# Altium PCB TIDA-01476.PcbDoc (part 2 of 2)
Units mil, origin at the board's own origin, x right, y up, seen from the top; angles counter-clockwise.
Board outline 2952.76 x 1377.95 mil, 4 copper layers (Layer 1 - Top Layer, Layer 2 - GND, Layer 3 - PWR, Layer 4 - Bottom Layer), stack 32.668 mil thick; 140 components, 50 nets, 358 pads, 357 vias.
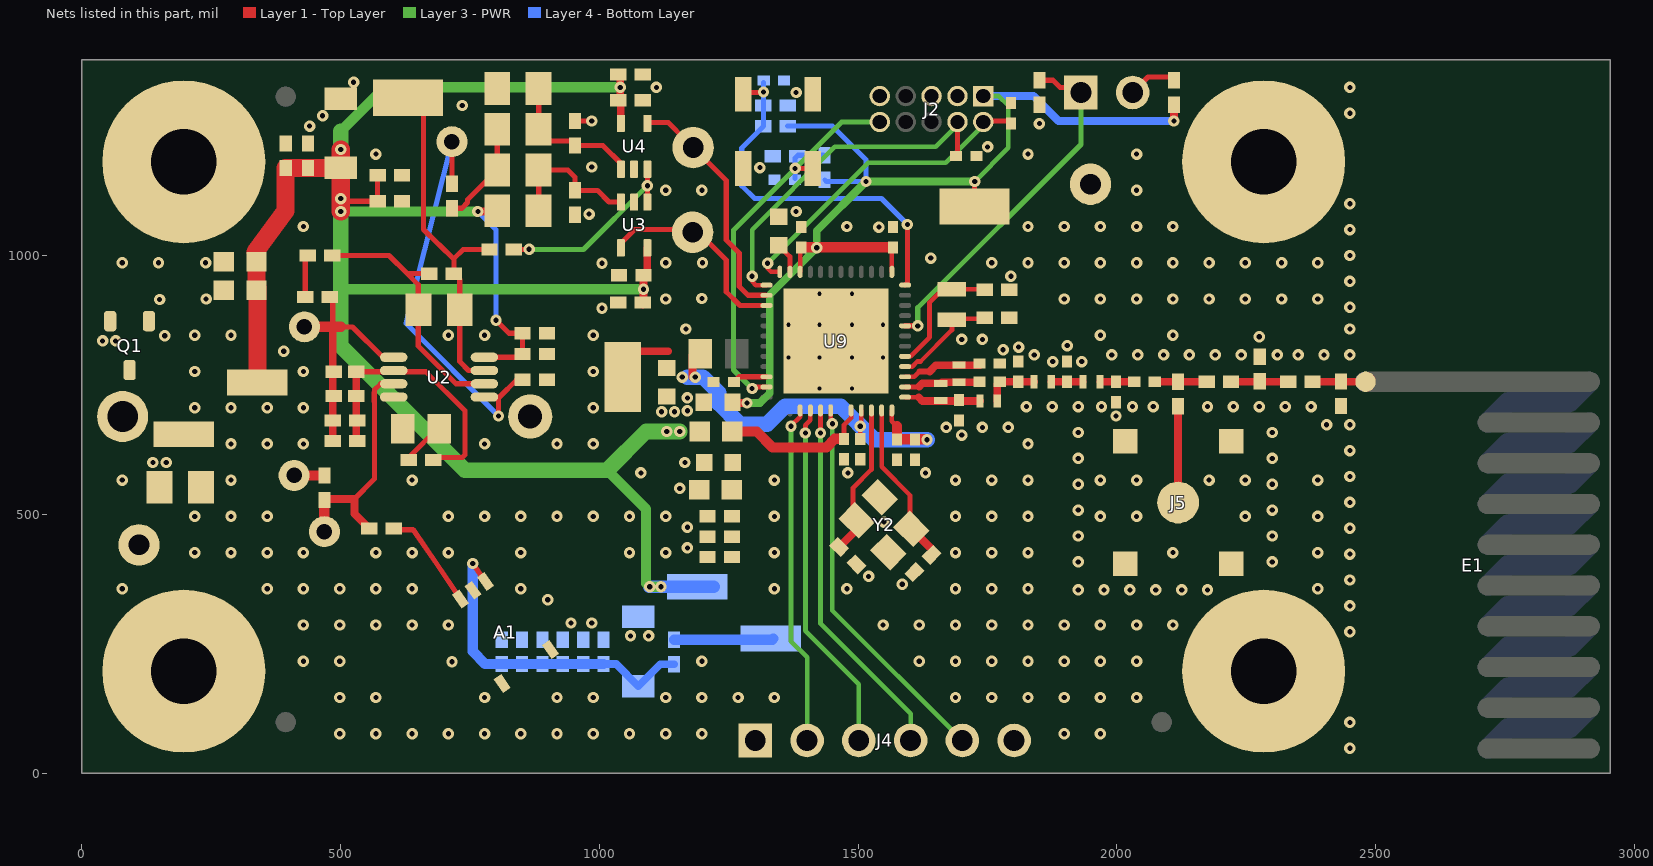
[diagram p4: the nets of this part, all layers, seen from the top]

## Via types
v1: diameter 22, hole 10, Layer 1 - Top Layer to Layer 4 - Bottom Layer, tented both sides, 323 vias
v2: diameter 39.37, hole 14.96, Layer 1 - Top Layer to Layer 4 - Bottom Layer, 19 vias
v3: diameter 19.68, hole 7.87, Layer 1 - Top Layer to Layer 4 - Bottom Layer, 12 vias
v4: diameter 22, hole 10, Layer 1 - Top Layer to Layer 4 - Bottom Layer, 3 vias

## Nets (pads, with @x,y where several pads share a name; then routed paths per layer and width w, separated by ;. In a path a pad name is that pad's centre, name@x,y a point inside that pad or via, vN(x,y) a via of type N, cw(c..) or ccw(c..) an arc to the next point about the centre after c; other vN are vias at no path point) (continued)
GND: A1.2 A1.4 A1.5 BT1.2 C1.2 C2.2 C3.2 C4.2 C5.2 C6.2 C7.2 C8.2 C9.2 C10.2 C11.2 C12.2 C13.2 C14.1 C16.1 C18.1 C19.2 C20.1 C22.2 C23.2 C24.1 C25.2 C26.2 C27.2 C28.2 C29.2 C30.1 C31.2 C32.2 C33.2 C34.2 C35.2 C36.2 C37.2 C38.2 C39.2 C40.1 C41.1 C42.1 C43.1 C44.2 C45.2 C46.2 C48.2 C49.2 C50.2 C53.2 C54.2 C55.2 C56.2 C57.2 H1.1 H4.1 H6.1 H8.1 J2.3 J2.5 J2.9 J4.1 J4.6 J5.2 J5.3 J5.4 J5.5 L8.2 pad.0@410,575 Q1.1 R4.1 R11.1 R15.1 S1.1 S2.1 TP1.1 TP2.1 U2.4 U3.2 U4.2 U5.2 U6.2 U7.2 U8.2 U9.49 Y2.2 Y2.4 | length 90.6
  Layer 1 - Top Layer w10: C23.2@952.76,1259.84 v1@984.84,1259.84
  Layer 1 - Top Layer w20: pad.0@410,575 R4.1@468.5,574.8
  other v1: 2450,48 498,76 568,76 638,76 708,76 778,76 848,76 918,76 988,76 1058,76 1128,76 1198,76 1898,76 1968,76 2450,98 498,146 568,146 778,146 918,146 988,146 1128,146 1198,146 1268,146 1338,146 1688,146 1758,146 1828,146 1898,146 1968,146 2038,146 715,215 428,216 498,216 1198,216 1618,216 1688,216 1758,216 1828,216 1898,216 1968,216 2038,216 1060,265 1095,265 2450,273 428,286 498,286 568,286 638,286 708,286 1548,286 1618,286 1688,286 1758,286 1828,286 1898,286 1968,286 2038,286 2108,286 945,290 985,290 2450,323 900,335 1925,354 1975,354 2025,354 2075,354 2125,354 2175,354 78,356 358,356 428,356 498,356 568,356 638,356 848,356 1338,356 1478,356 1688,356 1758,356 1828,356 2388,356 1585,365 2450,373 1520,380 1925,408 2300,408 2450,423 218,426 288,426 358,426 428,426 568,426 638,426 708,426 848,426 1058,426 1128,426 1338,426 1688,426 1758,426 1828,426 2108,426 2388,426 1170,435 1925,458 2300,458 2450,473 1170,475 1550,485 218,496 288,496 358,496 708,496 778,496 848,496 918,496 988,496 1058,496 1128,496 1338,496 1688,496 1758,496 1828,496 1968,496 2038,496 2248,496 2388,496 1925,508 2300,508 2450,523 1155,550 1925,558 2300,558 78,566 288,566 638,566 1338,566 1688,566 1758,566 1828,566 1968,566 2038,566 2178,566 2248,566 2388,566 2450,573 1080,580 1480,580 1630,580 1165,600 1925,608 2300,608 2450,623 288,636 358,636 428,636 778,636 918,636 988,636 1828,636 1700,653 1925,658 2300,658 1670,668 1740,668 1790,668 2405,673 2450,673 1998,690 1120,698 1145,698 1170,700 218,706 288,706 358,706 428,706 988,706 1825,708 1875,708 1925,708 1970,708 2030,708 2070,708 2175,708 2225,708 2275,708 2325,708 2375,708 1170,725 218,776 428,776 988,776 1876,795 1932,795 1840,808 1990,808 2040,808 2090,808 2140,808 2190,808 2240,808 2310,808 2350,808 2400,808 2450,808 390,815 1780,818 1810,823 1904,826 1700,838 1740,838 2275,843 160,845 218,846 288,846 708,846 778,846 988,846 1968,846 2108,846 1167,858 2450,858 1005,898 2450,900 150,915 240,916 1128,916 1898,916 1968,916 2038,916 2108,916 2178,916 2248,916 2318,916 2388,916 1198,917 2450,950 1795,960 1005,985 78,986 148,986 239,986 1128,986 1199,986 1758,986 1828,986 1898,986 1968,986 2038,986 2108,986 2178,986 2248,986 2318,986 2388,986 2450,1000 2450,1050 1540,1055 428,1056 1478,1056 1828,1056 1898,1056 1968,1056 2038,1056 2108,1056 980,1080 1380,1085 2450,1100 1128,1126 1198,1126 2038,1126 1310,1170 985,1171 568,1196 1828,1196 2038,1196 1750,1210 440,1250 1850,1255 985,1260 465,1270 2450,1275 1380,1315 1110,1325 2450,1325 525,1335
  other v3: 1425.06,743.11 1488.33,743.11 1365.16,803.01 1425.06,803.01 1488.33,803.01 1548.23,803.01 1365.16,866.28 1425.06,866.28 1488.33,866.28 1548.23,866.28 1425.06,926.18 1488.33,926.18
  other v4: 1640,995 735,1290
JTAG_TCK: J2.4 U7.1 U9.25 | length 676.6
  Layer 1 - Top Layer w9: v1(1295,960) 1295,950 1302.09,942.91 U9.25@1322.83,942.91 ; U7.1@1691.73,1192.6 J2.4@1691.73,1258.15
  Layer 3 - PWR w9: v1(1295,960) 1295,1050 1455,1210 1650,1210 J2.4@1691.73,1251.73
JTAG_TMS: J2.2 U6.1 U9.24 | length 611.6
  Layer 1 - Top Layer w9: v1(1325,985) 1325,975 1331.5,968.5 U9.24@1348.43,968.5 ; J2.2@1746.77,1260 U6.1@1795,1260
  Layer 3 - PWR w9: v1(1325,985) 1519,1179 1669,1179 J2.2@1741.73,1251.73
MODE_SELECTION: J3.1 R15.2 U9.8 | length 695.5
  Layer 1 - Top Layer w10: U9.8@1590.55,864.17 v1@1614.83,864.17 ; R15.2@1850.39,1338.58 1876.42,1338.58 1890,1325 1920.28,1325 J3.1@1930.32,1314.96
  Layer 3 - PWR w10: v1(1615,864) 1615,899 1930.32,1214.32 J3.1@1930.32,1314.96
NetA1_1: A1.1 C3.1 C5.1 C7.1 C9.1 C11.1 C12.1 C55.1 R2.1 | length 641.4
  Layer 1 - Top Layer w10: v1(755,405) A1.1@776.51,374.67
  Layer 4 - Bottom Layer w15: C3.1@1007.89,210.63 1032.44,210.63 C55.1@1075,168.07 1117.31,210.38 R2.1@1144,210.38
  Layer 4 - Bottom Layer w20: v1(755,405) 755,235 779.37,210.63 C12.1@811.04,210.63 C11.1@850.41,210.63 C7.1@929.15,210.63 C3.1@1007.89,210.63
NetA1_3: A1.3 R18.1 | length 195.1
  Layer 1 - Top Layer w10: R18.1@602.36,472.44 604.8,470 640,470 685,405 A1.3@728.14,340.8
NetBT1_1: BT1.1 Q1.3 | length 0
NetC13_1: C13.1 R3.1 | length 83.5
  Layer 1 - Top Layer w10: R3.1@631.38,610 C13.1@690.43,669.06
NetC15_1: C15.1 C17.2 D2.1 D3.2 pad.0@430,862.2 R5.2 U2.1 | length 490.4
  Layer 1 - Top Layer w10: C17.2@478.62,920 484.72,913.9 484.72,862.2 ; 500,862.2 522.8,862.2 581.61,803.39 U2.1@602.4,803.39
  Layer 1 - Top Layer w15: C15.1@484.72,641.73 484.72,862.2
  Layer 1 - Top Layer w20: pad.0@417.2,862.2 pad.0@430,862.2 484.72,862.2 500,862.2
NetC15_2: C15.2 D2.2 D3.1 R3.2 R5.1 U2.2 | length 524.4
  Layer 1 - Top Layer w10: D2.2@530,775.59 664.41,775.59 740,700 740,615 735,610 R3.2@678.62,610
  Layer 1 - Top Layer w15: D2.2@530,775.59 D3.1@530,728.35 530,643.7 C15.2@531.97,641.73
NetC17_1: C17.1 R6.1 | length 82.1
  Layer 1 - Top Layer w10: C17.1@431.38,920 431.38,995 R6.1@436.38,1000
NetC19_1: C19.1 pad.0@715,1220 R20.1 U2.5 | length 819.2
  Layer 1 - Top Layer w10: R20.1@715,1138.62 pad.0@715,1220 ; U2.5@777.6,726.61 806.61,726.61 840,760 C19.1@851.38,760 ; v1(805,690) 805,725
  Layer 4 - Bottom Layer w10: pad.0@715,1220 625.98,869.02 v1(805,690)
NetC21_1: C21.1 R7.2 R19.1 TP13.1 U2.7 | length 665.7
  Layer 1 - Top Layer w10: TP13.1@660,1300 660,1050 718.62,993.62 ; U2.7@777.6,777.8 747.2,777.8 730,795 R7.2@730,895 730,953.62 C21.1@718.62,965 718.62,993.62 ; R19.1@787.4,1011.81 736.81,1011.81 718.62,993.62
NetC21_2: C21.2 R6.2 R7.1 U2.6 | length 508.9
  Layer 1 - Top Layer w10: R6.2@483.62,1000 593.62,1000 628.62,965 ; C21.2@671.38,965 628.62,965 ; U2.6@777.6,752.2 722.8,752.2 650,825 R7.1@650,895 650,943.62 628.62,965
NetC22_1: C22.1 R8.1 R9.2 U3.3 | length 278
  Layer 1 - Top Layer w10: R8.1@882.52,1086.61 R9.2@882.52,1165.35 938.65,1165.35 952.76,1151.24 C22.1@952.76,1125.98 996.02,1125.98 1018.65,1103.35 U3.3@1041.34,1103.35
NetC23_1: C23.1 R10.1 R11.2 U4.1 | length 279.5
  Layer 1 - Top Layer w10: R11.2@882.52,1322.83 R10.1@882.52,1244.09 905.37,1221.24 952.76,1221.24 C23.1@952.76,1212.6 1006.4,1212.6 1041.34,1177.66 U4.1@1041.34,1168.31
NetC40_2: C40.2 U9.23 | length 60.2
  Layer 1 - Top Layer w9: C40.2@1346.46,1019.69 1368.11,998.03 U9.23@1368.11,968.5
NetC43_2: C43.2 L4.1 L5.1 U9.1 | length 146.5
  Layer 1 - Top Layer w9: U9.1@1590.55,726.38 1612.2,726.38 ; 1613,726 1617,726 ; L4.1@1659.45,719.61 L4.1@1660.06,719
  Layer 1 - Top Layer w15: 1617,726 1624,719 L4.1@1658.83,719 ; L4.1@1660.06,719 L5.1@1735.27,719
NetC47_1: C47.1 C48.1 L5.2 L6.1 | length 105
  Layer 1 - Top Layer w15: L5.2@1768.73,719 1768.73,751.14 C47.1@1773.62,756.03 C48.1@1809.06,756.03 L6.1@1839.57,756.03
NetC47_2: C47.2 L3.2 L4.2 U9.2 | length 139.7
  Layer 1 - Top Layer w9: U9.2@1590.55,746.06 1613,746.06
  Layer 1 - Top Layer w15: 1618,747 1624,753 1659.37,753 L4.2@1659.45,753.08 ; L4.2@1661.42,755.05 L3.2@1694.88,755.05 1733.27,755.05 C47.2@1734.25,756.03
NetC49_1: C49.1 L6.2 L7.1 | length 61
  Layer 1 - Top Layer w15: L6.2@1873.03,756.03 C49.1@1903.54,756.03 L7.1@1934.06,756.03
NetC50_1: C50.1 C51.2 L7.2 | length 65.9
  Layer 1 - Top Layer w15: L7.2@1967.52,756.03 C50.1@1998.03,756.03 C51.2@2033.46,756.03
NetC51_1: C51.1 R16.1 R17.1 | length 100.4
  Layer 1 - Top Layer w15: C51.1@2072.83,756.03 R16.1@2173.23,756.03
NetC52_1: C52.1 C54.1 R16.2 | length 110.2
  Layer 1 - Top Layer w15: R16.2@2220.47,756.03 C52.1@2330.71,756.03
NetC52_2: C52.2 E1.1 L8.1 | length 102.4
  Layer 1 - Top Layer w15: C52.2@2377.95,756.03 E1.1@2480.32,756.03
NetJ1_1: J1.1 R1.2
NetJ3_2: J3.2 R14.1 | length 95.2
  Layer 1 - Top Layer w10: J3.2@2030.32,1314.96 2030.32,1315.32 2060,1345 2103.82,1345 R14.1@2110.24,1338.58
NetJ4_2: J4.2 U9.39 | length 658.1
  Layer 1 - Top Layer w9: v1(1370,670) 1370,671 1387.8,688.8 U9.39@1387.8,700.79
  Layer 3 - PWR w9: v1(1370,670) 1370,255 1401.18,223.82 J4.2@1401.18,62.99
NetJ4_3: J4.3 U9.40 | length 684.5
  Layer 1 - Top Layer w9: v1(1398,657) 1398,672 1407.48,681.48 U9.40@1407.48,700.79
  Layer 3 - PWR w9: v1(1398,657) 1398,275 1501.18,171.82 J4.3@1501.18,62.99
NetJ4_4: J4.4 U9.41 | length 712.9
  Layer 1 - Top Layer w9: v1@1425,655 v1(1427.17,657.17) U9.41@1427.17,700.79
  Layer 3 - PWR w9: v1(1427.17,657.17) 1427.17,288.83 1601.18,114.82 J4.4@1601.18,62.99
NetJ4_5: J4.5 U9.42 | length 743.1
  Layer 1 - Top Layer w9: U9.42@1446.85,700.79 1446.85,678.15 v1(1450,675)
  Layer 3 - PWR w9: v1(1450,675) 1450,314.17 J4.5@1701.18,62.99
NetJ5_1: J5.1 R17.2 | length 186.1
  Layer 1 - Top Layer w15: J5.1@2118.11,514.69 R17.2@2118.11,700.79
NetJ6_1: J6.1 R2.2 | length 193
  Layer 4 - Bottom Layer w20: R2.2@1144,257.62 1333.62,257.62 J6.1@1336,260
NetQ1_2: Q1.2 R1.1
  other v1: 137,600 163,600 40,835 65,835
NetR4_2: pad.0@468.5,466.39 R4.2 R18.2 U2.3 | length 457.9
  Layer 1 - Top Layer w10: 526.57,529.53 565,567.95 565,718.27 564.92,718.35 564.92,734.8 565,734.88 565,740 577.2,752.2 U2.3@602.4,752.2
  Layer 1 - Top Layer w15: R4.2@468.5,527.56 470.47,529.53 526.57,529.53 526.57,500.98 R18.2@555.12,472.44
  Layer 1 - Top Layer w20: pad.0@468.5,466.39 R4.2@468.5,527.56
NetR9_1: R9.1 R10.2 R20.2 | length 200.2
  Layer 1 - Top Layer w10: R20.2@715,1091.38 734.12,1091.38 745,1102.26 745,1107.83 R9.1@802.52,1165.35 R10.2@802.52,1244.09
NetR19_2: R19.2 U3.1 U4.3 | length 373.9
  Layer 1 - Top Layer w10: R19.2@834.65,1011.81 863.81,1011.81 v1(864,1012) ; U3.1@1092.52,1103.35 v1(1092.52,1135) U4.3@1092.52,1168.31
  Layer 3 - PWR w10: v1@864,1011.81 969.33,1011.81 v1(1092.52,1135)
NRESET: C30.2 J2.10 R13.1 S2.2 U8.1 U9.35 | length 850.2
  Layer 1 - Top Layer w9: v1@1298.06,746.06 U9.35@1322.83,746.06
  Layer 1 - Top Layer w10: v1(1295,743) v1@1298.06,746.06 ; v1(1378.09,1168.3) v1(1378.09,1168.3) S2.2@1411.93,1168.26
  Layer 3 - PWR w10: v1(1295,743) 1259,779 1259,1049 1468.15,1258.15 J2.10@1541.73,1258.15
  Layer 4 - Bottom Layer w10: U8.1@1378.05,1148.59 1378.05,1187.96 C30.2@1381.99,1191.9 1383.96,1193.87 R13.1@1433.17,1193.87
PIR_OUT_HI: TP6.1 U3.4 U9.27 | length 402.1
  Layer 1 - Top Layer w10: U3.4@1041.34,1014.76 1041.34,1023.66 1067.68,1050 1175.98,1050 1181.1,1055.12 1245,991.22 1245,930 1271.46,903.54 U9.27@1322.83,903.54
PIR_OUT_LO: TP7.1 U4.4 U9.26 | length 510.3
  Layer 1 - Top Layer w10: U4.4@1092.52,1256.89 1132.87,1256.89 TP7.1@1165.87,1223.9 ; TP7.1@1151.1,1223.9 TP7.1@1165.87,1223.9 ; TP7.1@1181.1,1208.66 TP7.1@1165.87,1223.9 ; U9.26@1322.83,923.23 1286.77,923.23 1270,940 1270,1005 1245,1030 1245,1145 1166.1,1223.9 TP7.1@1165.87,1223.9
RX_TX: C44.1 L3.1 U9.3 | length 154.1
  Layer 1 - Top Layer w9: U9.3@1590.55,765.75 1608.27,765.75 1618.52,776
  Layer 1 - Top Layer w12: 1618.52,776 1631,776 ; 1630.59,776 1638,776
  Layer 1 - Top Layer w15: 1638,776 1650,788 C44.1@1735,788
USR_BTN: C24.2 R12.1 S1.2 U5.1 U9.12 | length 727.3
  Layer 1 - Top Layer w10: S1.2@1278.07,1312 1281.07,1315 1315.97,1315 v1(1316.97,1316) ; U9.12@1590.55,942.91 1595,947.36 v4(1595,1060)
  Layer 4 - Bottom Layer w10: U5.1@1316.97,1334.41 v1(1316.97,1316) 1316.97,1250 1275,1208.03 1275,1135 1300,1110 1545,1110 v4(1595,1060)
V_BATT: C1.1 C2.1 C4.1 C6.1 C8.1 C10.1 C14.2 C16.2 C18.2 C20.2 C53.1 C56.1 C57.1 J1.2 J6.2 L1.2 R8.2 U2.8 U3.5 U4.5 | length 4427.9
  Layer 1 - Top Layer w10: v1@505,1105 C16.2@571.38,1105 C53.1@571.38,1155 ; U2.8@777.6,803.39 844.76,803.39 C10.1@851.38,810 C14.2@851.38,850 825,850 v1(800,875)
  Layer 1 - Top Layer w15: v1(765,1085) 800.91,1085 R8.2@802.52,1086.61 ; C57.1@1040,1350 v1(1040,1325) 1040,1302.46 1041.85,1300.61 1041.34,1300.1 U4.5@1041.34,1256.89 ; C56.1@1083.62,905 1085,906.38 v1(1085,935) 1085.16,935.16 C18.2@1085.16,962.03 1092.52,969.39 U3.5@1092.52,1014.76
  Layer 1 - Top Layer w35: 335,1006.89 393.7,1086.61 C8.1@393.7,1169.29 C6.1@437.01,1169.29 C1.1@500,1169.29 ; C4.1@337.28,933.07 C2.1@337.28,988.19 ; J1.2@339,768 C4.1@339,938.35 ; v1(500,1085) v1(500,1110) C1.1@500,1169.29 ; v1(500,1205) C1.1@500,1169.29
  Layer 3 - PWR w20: 500,935 v1(1085,935) ; v1(500,1085) v1(765,1085) ; 500,1240 585,1325 v1(1040,1325) ; 1015,585 1090,510 1090,367 v1(1097,360) v1(1119,360)
  Layer 3 - PWR w30: 500,1240 v1(500,1205) v1(500,1110) v1(500,1085) 500,935 500,825 740,585 1015,585 1090,660 v1(1130,660) v1(1155,660)
  Layer 4 - Bottom Layer w10: v1(765,1085) 800,1050 v1(800,875)
  Layer 4 - Bottom Layer w25: v1(1097,360) v1(1119,360) J6.2@1189.13,360 J6.2@1220,360
VDDR: C32.1 C34.1 C36.1 C38.1 L2.2 TP9.1 U9.45 U9.48 | length 849.4
  Layer 1 - Top Layer w9: C34.1@1503.94,645.67 1503.94,670 1505.91,671.97 U9.45@1505.91,700.79 ; U9.48@1564.96,700.79 1564.96,680.04 1575,670
  Layer 1 - Top Layer w15: TP9.1@1054,815 1132.87,815 ; v1@1180,765 L2.2@1180,807.5
  Layer 1 - Top Layer w20: 1575,670 C36.1@1575,644.68 C38.1@1610,644.68 v1@1633,644.68
  Layer 4 - Bottom Layer w30: v1@1170,765 1180,765 1200,765 1230,735 1230,715 1271,674 1324,674 1359,709 1466,709 1531,644 1571,644 v1(1633,644)
  other v1: 1504,670 1160,765 1185,765
VDDS: C25.1 C26.1 C27.1 C28.1 C29.1 C31.1 C33.1 C35.1 C37.1 C39.1 J2.1 L1.1 R12.2 R13.2 R14.2 TP8.1 U9.13 U9.22 U9.34 U9.44 | length 2403.5
  Layer 1 - Top Layer w9: C37.1@1256.89,716.54 C37.1@1258.43,715 ; U9.22@1387.8,968.5 1387.8,1013.78 C33.1@1389.76,1015.75 ; C35.1@1472.44,645.67 1472.44,672.44 1486.22,686.22 U9.44@1486.22,700.79 ; U9.13@1564.96,968.5 1564.96,1013.78 C31.1@1566.93,1015.75
  Layer 1 - Top Layer w10: C39.1@1259.84,755.91 1269.68,765.75 U9.34@1322.83,765.75 ; TP8.1@1724.41,1106.3 v1@1724.41,1143
  Layer 1 - Top Layer w15: C37.1@1258.43,715 v1(1285,715) ; v1(2110,1260) 2110.24,1260.24 R14.2@2110.24,1291.34
  Layer 1 - Top Layer w20: L1.1@1256.5,660 1304,660 1335,629 1438,629 1454.67,645.67 C35.1@1472.44,645.67 ; C33.1@1389.76,1015.75 C31.1@1566.93,1015.75
  Layer 3 - PWR w9: v1(1725,1143) 1790,1208 1790,1290 1771.85,1308.15 J2.1@1741.73,1308.15
  Layer 3 - PWR w15: v1(1285,715) 1310,715 1329,734 1329,924 v1(1420,1015) 1420,1048 v1(1515,1143) v1(1725,1143) v1@1727.19,1143
  Layer 4 - Bottom Layer w9: R13.2@1435,1146.38 1438.38,1143 v1(1515,1143)
  Layer 4 - Bottom Layer w10: R12.2@1363.62,1250 1450,1250 1515,1185 v1(1515,1143)
  Layer 4 - Bottom Layer w15: J2.1@1741.73,1308.15 1838.85,1308.15 1887,1260 v1(2110,1260)
X24M_N: C46.1 U9.46 Y2.3 | length 288.3
  Layer 1 - Top Layer w9: Y2.3@1495,495 1490,500 1490,551 1525.59,586.59 U9.46@1525.59,700.79
  Layer 1 - Top Layer w15: C46.1@1463.3,436.7 1497.11,470.51 Y2.3@1497.11,488.35
X24M_P: C45.1 U9.47 Y2.1 | length 304.5
  Layer 1 - Top Layer w9: U9.47@1545.28,700.79 1545.28,591.72 1600,537 Y2.1@1600,485
  Layer 1 - Top Layer w15: Y2.1@1602.89,471.65 1641.7,432.84 C45.1@1641.7,421.7
X32K_Q1: C42.2 U9.4 Y1.1 | length 199.6
  Layer 1 - Top Layer w9: U9.4@1590.55,785.43 1604.33,785.43 1614.17,795.28 1620.28,795.28 1681.1,856.1 Y1.1@1681.1,875.98 1683.07,877.95 C42.2@1740.16,877.95
X32K_Q2: C41.2 U9.5 Y1.2 | length 243.9
  Layer 1 - Top Layer w9: U9.5@1590.55,805.12 1601.12,805.12 1637.8,841.8 1637.8,909.45 1663.39,935.04 Y1.2@1681.1,935.04 1738.19,935.04 C41.2@1740.16,933.07
pads on no net: E1. FID1.1 FID2.1 FID3.1 FID4.1 FID5.1 FID6.1 J2.6 J2.7 J2.8 SH-J1.0 SH-J3.0 SH-J6.0 U9.6 U9.7 U9.9 U9.10 U9.11 U9.14 U9.15 U9.16 U9.17 U9.18 U9.19 U9.20 U9.21 U9.28 U9.29 U9.30 U9.31 U9.32 U9.36 U9.37 U9.38 U9.43
copper on no net:
  other v2: 2716.54,47.37 2913.39,47.37 2716.54,126.11 2913.39,126.11 2716.54,204.85 2913.39,204.85 2716.54,283.59 2913.39,283.59 2716.54,362.33 2913.39,362.33 2716.54,441.07 2913.39,441.07 2716.54,519.81 2913.39,519.81 2716.54,598.55 2913.39,598.55 2716.54,677.29 2913.39,677.29 2913.39,756.03

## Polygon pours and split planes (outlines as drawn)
GND on Layer 1 - Top Layer "Top Layer-No Net" (solid, remove dead copper, pour order 7): 25,1350 2475,1350 2475,25 25,25
GND on Layer 4 - Bottom Layer "Top Layer-No Net" (solid, remove dead copper, pour order 11): 25,1350 2475,1350 2475,25 25,25
GND on Layer 3 - PWR "Top Layer-No Net" (solid, remove dead copper, pour order 10): 25,1350 2475,1350 2475,25 25,25
NetQ1_2 on Layer 3 - PWR "Top Layer-No Net" (solid, remove dead copper, pour order 9): 25,855 85,855 95,855 150.53,799.47 195,755 195,675 195,590 125,590 125,650 140,665 140,680 140,710 25,825 25,840 25,842.03
GND on Layer 2 - GND "Top Layer-No Net" (solid, remove dead copper, pour order 8): 25,1350 2475,1350 2475,25 25,25

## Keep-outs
Keep-Out Layer:
  lines w10: -5,0 ccw(c0,0) 0,-5 ; -5,0 ccw(c0,0) 0,-5 ; -5,0 -5,1377.95 ; -5,1377.95 cw(c0,1377.95) 0,1382.95 ; -5,1377.95 cw(c0,1377.95) 0,1382.95 ; 0,-5 2952.76,-5 ; 0,1382.95 2952.76,1382.95 ; 2952.76,-5 ccw(c2952.76,0) 2957.76,0 ; 2952.76,-5 ccw(c2952.76,0) 2957.76,0 ; 2952.76,1382.95 cw(c2952.76,1377.95) 2957.76,1377.95 ; 2952.76,1382.95 cw(c2952.76,1377.95) 2957.76,1377.95 ; 2957.76,0 2957.76,1377.95
  text ".Layer_Name" at 577,-858.49 h60

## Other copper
Layer 1 - Top Layer:
  rectangle net V_BATT: 1155,650 1205,670
  rectangle net VDDS: 1245,405 1270,770
  rectangle net VDDR: 1110,754 1197,837
  rectangle net NetBT1_1: 51.18,690 105,800
  rectangle net NetJ1_1: 205,559 255,679
  rectangle net V_BATT: 1115,640 1210,680
  rectangle net NetQ1_2: 25,820 80,895
  rectangle net NetQ1_2: 125,520 175,611
  pour cut-out: 167.05,515 212.95,515 212.95,510.6 170.88,510.6 169.41,512.07
  pour cut-out: 1597.64,957.93 1643.54,957.93 1643.54,953.53 1601.47,953.53 1600,955
  region net DCDC_SW: 1333,781 1240,781 1240,840 1285,840 1295,832 1295,802 1305,792 1333,792
  pour cut-out: 2464.57,0 2952.76,0 2952.76,1377.95 2464.57,1377.95
  pour cut-out: 1705,958 1774,958 1774,859 1706,859 1705,860
  pour cut-out: 785,1350 905,1350 905,1045 785,1045
  pour cut-out: 675,930 710,930 710,850 675,850
  pour cut-out: 1650,810 1763,810 1763,778 2465,778 2465,733 2142,733 2142,562 2096,562 2096,733 1792,733 1792,696 1616,696 1603,709 1603,763
  pour cut-out: 2061.33,522.38 ccw(c2118.33,522.38) 2118.33,465.38 ccw(c2118.33,522.38) 2175.33,522.38 ccw(c2118.33,522.38) 2118.33,579.38 ccw(c2118.33,522.38)
  text ".Layer_Name" at 577,-858.49 h60
Layer 2 - GND:
  pour cut-out: 2464.57,0 2952.76,0 2952.76,1377.95 2464.57,1377.95
  text ".Layer_Name" at 577,-858.49 h60
Layer 3 - PWR:
  rectangle net V_BATT: 1080,344.86 1134.14,380
  pour cut-out: 2464.57,0 2952.76,0 2952.76,1377.95 2464.57,1377.95
  text ".Layer_Name" at 577,-858.49 h60
Layer 4 - Bottom Layer:
  rectangle net VDDR: 1140,750 1190,780
  pour cut-out: 1715,1350 1715,1335 1720,1335 1720,1350.08
  pour cut-out: 2464.57,0 2952.76,0 2952.76,1377.95 2464.57,1377.95
  text ".Layer_Name" at 577,-858.49 h60

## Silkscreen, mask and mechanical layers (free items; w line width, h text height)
Top Overlay:
  text ".TID" at 1673.78,296.18 h60
  text "Rev .PCB_Rev" at 1910,245 h60
  text ".Layer_Name" at 577,-858.49 h60
Bottom Overlay:
  text ".Layer_Name" at 577,-858.49 h60
Top Paste:
  text ".Layer_Name" at 577,-858.49 h60
Bottom Paste:
  text ".Layer_Name" at 577,-858.49 h60
Top Solder:
  text ".Layer_Name" at 577,-858.49 h60
  text ".Layer_Name" at 577,-858.49 h60
Bottom Solder:
  text ".Layer_Name" at 577,-858.49 h60
Drill Guide:
  text ".Layer_Name" at 577,-858.49 h60
M1 Board Outline:
  the board outline again, w10
  text "SLOT" at 980,290 h40 r30.14
  text "SLOT" at 635,90 h40 r30.14
  text ".Layer_Name" at 577,-858.49 h60
M2 Board Dimensions:
  rectangle: 0,-275 125,-150
  rectangle: 125,-400 500,-275
  lines w7: 0,-275 1000,-275 ; 125,-400 125,-150 ; 250,-400 250,-150 ; 500,-400 500,-150 ; 750,-400 750,-150 ; 0,-400 1000,-400 1000,-150 0,-150 0,-400
  text ".Layer_Name" at 577,-858.49 h60
M3 3D STEP Top:
  text ".Layer_Name" at 577,-858.49 h60
M4 3D STEP Bottom:
  text ".Layer_Name" at 577,-858.49 h60
M5 Assembly Top:
  lines w10: -292,-930.17 6308,-930.17 ; -292,-726.83 6310,-726.83 ; -292,-523.5 -292,-1133.5 3713,-1133.5 6310,-1133.5 6310,-523.5 -291.5,-523.5 -291.5,-1133.5 1284,-1133.5 ; 2173,-1133.5 2173,-523.5 ; 3440,-726.83 3440,-523.5 ; 4280,-726.83 4280,-523.5 ; 4902,-1140 4902,-937.17
  text "COMPONENTS MARKED 'DNP' SHOULD NOT BE POPULATED." at 1153.5,-318.5 h60
  text "ASSEMBLY VARIANT:" at 1153,-434 h60
  text ".VariantName" at 2189,-434 h60
  text "PCB VIEWED FROM TOP SIDE" at -228.5,-655.67 h60
  text "BOARD #:" at 2248,-655.67 h60
  text ".PRJ_Number" at 2793.5,-655.67 h60
  text "REV:" at 3638,-655.67 h60
  text ".PCB_Rev" at 3929.5,-655.67 h60
  text "SVN REV:" at 4476,-655.67 h60
  text ".VersionControl_RevNumber" at 4982,-655.67 h60
  text "TID #:" at 2248,-859 h60
  text ".TID" at 2793.5,-859 h60
  text "PLOT NAME =" at -228.5,-1064.34 h60
  text ".plot_File_Name" at 577,-1064.34 h60
  text "GENERATED    :" at 2250,-1064.34 h60
  text ".Print_Date" at 3119.5,-1064.34 h60
  text ".Print_Time" at 3848.5,-1064.34 h60
  text "TEXAS INSTRUMENTS" at 5113,-1064.34 h60
M6 Assembly Bottom:
  lines w10: -292.5,-727.33 6309.5,-727.33 ; -290.5,-930.67 6309.5,-930.67 ; 1115.5,-1140.5 1115.5,-937.67 ; 1737.5,-727.33 1737.5,-524 ; 2577.5,-727.33 2577.5,-524 ; 3844.5,-1134 3844.5,-524 ; 4733.5,-1134 6309,-1134 6309,-524 -292.5,-524 -292.5,-1134 2304.5,-1134 6309.5,-1134 6309.5,-524
  text "COMPONENTS MARKED 'DNP' SHOULD NOT BE POPULATED." at 6102,-318 h60
  text ".VariantName" at 5058,-434 h60
  text "ASSEMBLY VARIANT:" at 6097,-434 h60
  text ".VersionControl_RevNumber" at 1035.5,-656.17 h60
  text "SVN REV:" at 1541.5,-656.17 h60
  text ".PCB_Rev" at 2088,-656.17 h60
  text "REV:" at 2379.5,-656.17 h60
  text ".PRJ_Number" at 3224,-656.17 h60
  text "BOARD #:" at 3769.5,-656.17 h60
  text "PCB VIEWED FROM BOTTOM SIDE" at 6246,-656.17 h60
  text ".TID" at 3224,-859.5 h60
  text "TID #:" at 3769.5,-859.5 h60
  text "TEXAS INSTRUMENTS" at 904.5,-1064.84 h60
  text ".Print_Time" at 2169,-1064.84 h60
  text ".Print_Date" at 2898,-1064.84 h60
  text "GENERATED    :" at 3767.5,-1064.84 h60
  text ".plot_File_Name" at 5440.5,-1064.84 h60
  text "PLOT NAME =" at 6246,-1064.84 h60
M9 Title Sheet:
  drawing of 57 lines, arcs and shapes, not listed
  text "1" at 739.84,8036.5 h70
  text "2" at 3235.5,8036.5 h70
  text "3" at 5724.84,8036.5 h70
  text "4" at 8231.51,8036.5 h70
  text "5" at 10730.5,8036.5 h70
  text "6" at 13235.5,8036.5 h70
  text "A" at -416.5,6893.5 h70
  text "A" at 14383.5,6893.5 h70
  text "B" at -416.5,4513.5 h70
  text "B" at 14383.5,4513.5 h70
  text "C" at -416.5,2138.5 h70
  text "C" at 14383.5,2138.5 h70
  text "PROJECT TITLE:" at 11343.5,277.5 h45
  text ".PRJ_Title" at 11393.5,144.17 h70
  text "DESIGNED FOR:" at 11343.5,-23.5 h45
  text ".PRJ_Customer" at 11393.5,-163.5 h70
  text "D" at -416.5,-231.5 h70
  text "D" at 14383.5,-231.5 h70
  text "FILE NAME:" at 11343.5,-323.5 h45
  text ".PCB_File_Name_No_Path" at 11393.5,-443.5 h70
  text "Texas Instruments (TI) and/or its licensors do not warrant the accuracy or completeness of this specification" at 6374,-605.34 h45
  text "ENGINEER:" at 11343.5,-613.5 h45
  text "LAYOUT BY:" at 12848.5,-613.5 h45
  text "or any information contained therein. TI and/or its licensors do not warrant that this design will meet" at 6329.01,-718 h45
  text ".PRJ_Engineer" at 11393.5,-768.49 h70
  text ".PCB_Layout" at 12899,-768.49 h70
  text "the specifications, will be suitable for your application or fit for any particular purpose, or will operate in" at 6329.01,-830.67 h45
  text ".Layer_Name" at 577,-858.49 h60
  text "ALTIUM DESIGNER VERSION:" at 12848.5,-923.5 h45
  text "an implementation. TI and/or its licensors do not warrant that the design is production worthy. You should" at 6329.01,-943.33 h45
  text "completely validate and test your design implementation to confirm the system functionality for your application." at 6374,-1056 h45
  text ".print_Scale" at 11393.5,-1056.83 h70
  text ".Application_BuildNumber" at 12899,-1056.83 h70
  text "1" at 739.84,-1263.5 h70
  text "2" at 3235.5,-1263.5 h70
  text "3" at 5724.84,-1263.5 h70
  text "4" at 8231.51,-1263.5 h70
  text "5" at 10730.5,-1263.5 h70
  text "6" at 13235.5,-1263.5 h70
M10 Fab Notes:
  drawing of 186 lines, arcs and shapes, not listed
  text "DESIGN INFORMATION" at 12381.02,5910 h60
  text "MIN. TRACK WIDTH:" at 11736.46,5730 h60
  text "6" at 12832.7,5730 h60
  text "MIL" at 12987.46,5730 h60
  text "Impedance Control:" at 6857,5615 h200
  text "MIN. CLEARANCE:" at 11736.46,5598 h60
  text "6" at 12772.7,5598 h60
  text "mm" at 12987.46,5598 h60
  text "MIN. VIA PAD SIZE:" at 11736.46,5466 h60
  text "20" at 12802.71,5466 h60
  text "MIL" at 12987.46,5466 h60
  text "- Top layer contains 50 ohm impedance (+/- 10%) single ended using 15 mil lines (from E1 to U9)" at 6857,5375 h100
  text "0.05mm (2MIL)" at 12431.46,5324.29 h60
  text "MINIMUM ANNULAR RING" at 11407.23,5320 h60
  text "EXTERNAL" at 13139.46,5320 h60
  text "PER" at 11607.23,5202 h60
  text "IPC-D-275 CLASS 2 LEVEL C" at 11827.23,5202 h60
  text "MIL, HOLES" at 13315.46,5089.71 h60
  text "+/-" at 12923,5089 h60
  text "+/-" at 13777,5089 h60
  text "REGISTRATION TOLERANCES:" at 11407.23,5084 h60
  text "METAL" at 12607,5084 h60
  text "5" at 13183.2,5084 h60
  text "3" at 14016.2,5084 h60
  text "MIL" at 14132.46,5084 h60
  text "MATERIAL:" at 11332.46,4874.54 h60
  text "FR-4 High Tg" at 12318.9,4734.21 h60
  text "FR-408" at 11753.46,4725.64 h60
  text "X" at 12165.46,4725.64 h60
  text "OTHER" at 13241.46,4725.64 h60
  text "62 MIL (1.6mm) +/-10%" at 12073.56,4562.92 h60
  text "THICKNESS:" at 11407.23,4558.64 h60
  text "33 MIL (0.8mm) +/-10%" at 13348.56,4557.92 h60
  text "X" at 13230,4550 h60
  text "TOLERANCE:" at 11407.23,4400.64 h60
  text "X" at 12246.53,4400.64 h60
  text "ANSI IPC-6012 TYPE 3 CLASS 2" at 12433.48,4400.64 h60
  text "OTHER +/-" at 12433.46,4244.64 h60
  text "BOW & TWIST:" at 11407.23,4087.64 h60
  text "X" at 12246.53,4087.64 h60
  text "ANSI IPC-6012 TYPE 3 CLASS 2" at 12433.48,4087.64 h60
  text "OTHER +/-" at 12433.46,3929.13 h60
  text "DRILLING:" at 11332.46,3790.64 h60
  text "REFERENCE:" at 11407.23,3673.64 h60
  text "X" at 12055.46,3673.64 h60
  text "AS SHOWN" at 12242.46,3673.64 h60
  text "X" at 12956.46,3673.64 h60
  text "NC_DRILL FILES" at 13093.46,3673.64 h60
  text "PTH MIN COPPER THICKNESS:" at 11407.23,3515.64 h60
  text "X" at 12757.46,3515.64 h60
  text "1MIL" at 12894.46,3515.64 h60
  text "OTHER" at 13391.46,3515.64 h60
  text "BOARD FINISH:" at 11332.46,3356.64 h60
  text "SILKSCREEN:" at 11487.68,3238.64 h60
  text "X" at 12436.46,3238.64 h60
  text "TOP" at 12562.46,3238.64 h60
  text "X" at 12946.46,3238.64 h60
  text "BOTTOM" at 13073.46,3238.64 h60
  text "SILKSCREEN COLOR:" at 11487.68,3071.64 h60
  text "X" at 12435.42,3071.64 h60
  text "WHITE" at 12562.46,3071.64 h60
  text "OTHER" at 13073.46,3071.64 h60
  text "SOLDER RESIST COLOR:" at 11487.68,2901.64 h60
  text "X" at 12055.42,2742.44 h60
  text "GREEN" at 12182.46,2742.44 h60
  text "BLUE" at 12773.46,2742.44 h60
  text "OTHER" at 13311.46,2742.44 h60
  text "IMMERSION GOLD (ENIG)" at 12393.46,2553.92 h60
  text "ENEPIG" at 13731,2550.64 h60
  text "SURFACE FINISH:" at 11332.46,2549.64 h60
  text "X" at 12206.51,2549.64 h60
  text "IMM. TIN/SILVER OR EQUIV" at 11662,2392.64 h60
  text "OTHER" at 13093.46,2392.64 h60
  text "ARRAY/PANEL:" at 11332.46,2213.64 h60
  text "CUT AND TRIM PER MECH LAYER 1" at 12393.46,2209.35 h60
  text "N.C. ROUTE" at 12393.46,2057.64 h60
  text "X" at 13072.46,2057.64 h60
  text "V. SCORE" at 13259.46,2057.64 h60
  text "CERTIFICATION:" at 11332.46,1920.64 h60
  text "MATERIALS AND WORKMANSHIP FOR ALL PCBS" at 12057.46,1920.64 h60
  text "TO MEET OR EXCEED THE REQUIREMENTS OF:" at 12057.46,1822.64 h60
  text "X" at 11683.96,1686.13 h60
  text "ANSI IPC-A-600F CLASS ->" at 11822.96,1686.13 h60
  text "X" at 13462.02,1686.13 h60
  text "2" at 13580.96,1686.14 h60
  text "1" at 13265.96,1684.64 h60
  text "3" at 13934.96,1684.64 h60
  text "X" at 11686.02,1526.64 h60
  text "UL 94V-0" at 11822.96,1526.64 h60
  text "X" at 12498.02,1526.64 h60
  text "RoHS" at 12634.96,1526.64 h60
  text "OTHER" at 13279.36,1526.64 h60
  text "PER ORDER" at 13676.42,1526.64 h60
  text "ADDITIONAL REQUIREMENTS:" at 11332.46,1385.64 h60
  text "MICROSECTION:" at 11407.23,1270.64 h60
  text "YES" at 12312.96,1270.64 h60
  text "REQUIRED" at 13174.46,1114.49 h60
  text "BARE BOARD ELEC. TEST:" at 11407.23,1111.64 h60
  text "NONE" at 12712.96,1111.64 h60
  text "X" at 13047.46,1111.64 h60
  text "PER ORDER" at 13766.46,1111.64 h60
  text "MANUFACTURER'S UL:" at 11407.23,954.64 h60
  text "RAIL" at 12572.96,950.35 h60
  text "METAL" at 13064.77,950.35 h60
  text "X" at 13440,950 h60
  text "SILK" at 13576.46,950.35 h60
  text ".Layer_Name" at 577,-858.49 h60
M11 Gerber Information:
  lines w10: -292,-930.17 6308,-930.17 ; -292,-726.83 6310,-726.83 ; -292,-523.5 -292,-1133.5 3713,-1133.5 6310,-1133.5 6310,-523.5 -291.5,-523.5 -291.5,-1133.5 1284,-1133.5 ; 2173,-1133.5 2173,-523.5 ; 3440,-726.83 3440,-523.5 ; 4280,-726.83 4280,-523.5 ; 4902,-1140 4902,-937.17
  text "ALL ARTWORK VIEWED FROM TOP SIDE" at -228.5,-655.67 h60
  text "BOARD #:" at 2248,-655.67 h60
  text ".PRJ_Number" at 2793.5,-655.67 h60
  text "REV:" at 3638,-655.67 h60
  text ".PCB_Rev" at 3929.5,-655.67 h60
  text "SVN REV:" at 4476,-655.67 h60
  text ".VersionControl_RevNumber" at 4982,-655.67 h60
  text "LAYER NAME =" at -228.5,-858.49 h60
  text "TID #:" at 2248,-859 h60
  text ".TID" at 2793.5,-859 h60
  text "PLOT NAME =" at -228.5,-1064.34 h60
  text ".plot_File_Name" at 577,-1064.34 h60
  text "GENERATED    :" at 2250,-1064.34 h60
  text ".Print_Date" at 3119.5,-1064.34 h60
  text ".Print_Time" at 3848.5,-1064.34 h60
  text "TEXAS INSTRUMENTS" at 5113,-1064.34 h60
M12 Stackup:
  drawing of 295 lines, arcs and shapes, not listed
  text "Layer" at 9600,7635 h60
  text "Name" at 10009.91,7635 h60
  text "Material" at 10949.65,7635 h60
  text "Thickness" at 11809.42,7635 h60
  text "Constant" at 12459.26,7635 h60
  text "Board Layer Stack" at 13029.12,7635 h60
  text "1" at 9600,7515 h60
  text "Top Overlay" at 10009.91,7515 h60
  text "2" at 9600,7395 h60
  text "Top Solder" at 10009.91,7395 h60
  text "Solder Resist" at 10949.65,7395 h60
  text "0.40mil" at 11809.42,7395 h60
  text "3.5" at 12459.26,7395 h60
  text "3" at 9600,7275 h60
  text "Top Layer" at 10009.91,7275 h60
  text "Copper" at 10949.65,7275 h60
  text "1.42mil" at 11809.42,7275 h60
  text "4" at 9600,7155 h60
  text "Dielectric1" at 10009.91,7155 h60
  text "370HR" at 10949.65,7155 h60
  text "9.00mil" at 11809.42,7155 h60
  text "4.5" at 12459.26,7155 h60
  text "5" at 9600,7035 h60
  text "Signal Layer 1" at 10009.91,7035 h60
  text "Copper" at 10949.65,7035 h60
  text "1.42mil" at 11809.42,7035 h60
  text "6" at 9600,6915 h60
  text "Dielectric 3" at 10009.91,6915 h60
  text "370HR" at 10949.65,6915 h60
  text "9.00mil" at 11809.42,6915 h60
  text "4.5" at 12459.26,6915 h60
  text "7" at 9600,6795 h60
  text "Signal Layer 2" at 10009.91,6795 h60
  text "Copper" at 10949.65,6795 h60
  text "1.42mil" at 11809.42,6795 h60
  text "8" at 9600,6675 h60
  text "Dielectric 2" at 10009.91,6675 h60
  text "370HR" at 10949.65,6675 h60
  text "9.00mil" at 11809.42,6675 h60
  text "4.5" at 12459.26,6675 h60
  text "9" at 9600,6555 h60
  text "Bottom Layer" at 10009.91,6555 h60
  text "Copper" at 10949.65,6555 h60
  text "1.42mil" at 11809.42,6555 h60
  text "10" at 9600,6435 h60
  text "Bottom Solder" at 10009.91,6435 h60
  text "Solder Resist" at 10949.65,6435 h60
  text "0.40mil" at 11809.42,6435 h60
  text "3.5" at 12459.26,6435 h60
  text "11" at 9600,6315 h60
  text "Bottom Overlay" at 10009.91,6315 h60
  text ".Layer_Name" at 577,-858.49 h60
M13 Component Bodies Top:
  text ".Layer_Name" at 577,-858.49 h60
M14 Component Bodies Bottom:
  text ".Layer_Name" at 577,-858.49 h60
M15 Courtyards Top:
  text ".Layer_Name" at 577,-858.49 h60
M16 Courtyards Bottom:
  text ".Layer_Name" at 577,-858.49 h60
Drill Drawing:
  lines w10: 5536.09,2244.1 5591.34,2244.1 5591.34,2299.35 5536.09,2299.35 5536.09,2244.1 ; 5536.09,2382.23 5549.9,2382.23 5549.9,2368.42 5577.53,2368.42 5577.53,2382.23 5591.34,2382.23 5591.34,2409.86 5577.53,2409.86 5577.53,2423.67 5549.9,2423.67 5549.9,2409.86 5536.09,2409.86 5536.09,2382.23 ; 5536.09,2492.74 5536.09,2506.55 5549.9,2520.36 5536.09,2534.18 5536.09,2547.99 5549.9,2547.99 5563.72,2534.18 5577.53,2547.99 5591.34,2547.99 5591.34,2534.18 5577.53,2520.36 5591.34,2506.55 5591.34,2492.74 5577.53,2492.74 5563.72,2506.55 5549.9,2492.74 5536.09,2492.74 ; 5536.09,2630.87 5549.9,2630.87 5563.72,2617.06 5577.53,2630.87 5591.34,2630.87 5577.53,2644.68 5591.34,2658.5 5577.53,2658.5 5563.72,2672.31 5549.9,2658.5 5536.09,2658.5 5549.9,2644.68 5536.09,2630.87 ; 5536.09,2865.7 5563.72,2879.51 5591.34,2865.7 5577.53,2893.32 5591.34,2920.95 5563.72,2907.14 5536.09,2920.95 5549.9,2893.32 5536.09,2865.7 ; 5547.14,2255.15 5580.29,2255.15 5580.29,2288.3 5547.14,2288.3 5547.14,2255.15 ; 5547.14,2387.75 5555.43,2387.75 5555.43,2379.47 5572.01,2379.47 5572.01,2387.75 5580.29,2387.75 5580.29,2404.33 5572.01,2404.33 5572.01,2412.62 5555.43,2412.62 5555.43,2404.33 5547.14,2404.33 5547.14,2387.75 ; 5547.14,2503.79 5547.14,2512.07 5555.43,2520.36 5547.14,2528.65 5547.14,2536.94 5555.43,2536.94 5563.72,2528.65 5572.01,2536.94 5580.29,2536.94 5580.29,2528.65 5572.01,2520.36 5580.29,2512.07 5580.29,2503.79 5572.01,2503.79 5563.72,2512.07 5555.43,2503.79 5547.14,2503.79 ; 5547.14,2636.39 5555.43,2636.39 5563.72,2628.11 5572.01,2636.39 5580.29,2636.39 5572.01,2644.68 5580.29,2652.97 5572.01,2652.97 5563.72,2661.26 5555.43,2652.97 5547.14,2652.97 5555.43,2644.68 5547.14,2636.39 ; 5547.14,2876.75 5563.72,2885.03 5580.29,2876.75 5572.01,2893.32 5580.29,2909.9 5563.72,2901.61 5547.14,2909.9 5555.43,2893.32 5547.14,2876.75
  lines w12: 5486,2206.8 7464.02,2206.8 ; 5486,3325.68 7464.02,3325.68 ; 5823.86,2082.48 5823.86,3450 ; 6155.86,2082.48 6155.86,3450 ; 6792.43,2082.48 6792.43,3450 ; 7051.57,2082.48 7051.57,3450 ; 5486,2082.48 7464.02,2082.48 7464.02,3450 5486,3450 5486,2082.48
  text "Symbol" at 5560.59,3362.98 h72
  text "Quantity" at 5861.16,3362.98 h72
  text "Finished Hole Size" at 6193.16,3362.98 h72
  text "Plated" at 6829.72,3362.98 h72
  text "Hole Type" at 7088.86,3362.98 h72
  text "12" at 5861.16,3238.66 h60
  text "7.87mil (0.200mm)" at 6193.16,3238.66 h60
  text "PTH" at 6829.72,3238.66 h60
  text "Round" at 7088.86,3238.66 h60
  text "D" at 5535.31,3228.66 h55.25
  text "326" at 5861.16,3114.34 h60
  text "10.00mil (0.254mm)" at 6193.16,3114.34 h60
  text "PTH" at 6829.72,3114.34 h60
  text "Round" at 7088.86,3114.34 h60
  text "B" at 5535.31,3104.35 h55.25
  text "19" at 5861.16,2990.02 h60
  text "14.96mil (0.380mm)" at 6193.16,2990.02 h60
  text "PTH" at 6829.72,2990.02 h60
  text "Round" at 7088.86,2990.02 h60
  text "C" at 5535.31,2980.02 h55.25
  text "10" at 5861.16,2865.7 h60
  text "27.56mil (0.700mm)" at 6193.16,2865.7 h60
  text "PTH" at 6829.72,2865.7 h60
  text "Round" at 7088.86,2865.7 h60
  text "4" at 5861.16,2741.38 h60
  text "30.00mil (0.762mm)" at 6193.16,2741.38 h60
  text "PTH" at 6829.72,2741.38 h60
  text "Round" at 7088.86,2741.38 h60
  text "A" at 5535.31,2731.39 h55.25
  text "12" at 5861.16,2617.06 h60
  text "40.00mil (1.016mm)" at 6193.16,2617.06 h60
  text "PTH" at 6829.72,2617.06 h60
  text "Round" at 7088.86,2617.06 h60
  text "1" at 5861.16,2492.74 h60
  text "46.50mil (1.181mm)" at 6193.16,2492.74 h60
  text "PTH" at 6829.72,2492.74 h60
  text "Round" at 7088.86,2492.74 h60
  text "1" at 5861.16,2368.42 h60
  text "59.06mil (1.500mm)" at 6193.16,2368.42 h60
  text "PTH" at 6829.72,2368.42 h60
  text "Round" at 7088.86,2368.42 h60
  text "4" at 5861.16,2244.1 h60
  text "125.98mil (3.200mm)" at 6193.16,2244.1 h60
  text "PTH" at 6829.72,2244.1 h60
  text "Round" at 7088.86,2244.1 h60
  text "389 Total" at 5861.16,2119.78 h60
  text ".Layer_Name" at 577,-858.49 h60

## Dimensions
0,-400 to 1000,-400 on M2 Board Dimensions
0,0 to 0,1377.95 on M2 Board Dimensions
0,0 to 2952.76,0 on M2 Board Dimensions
